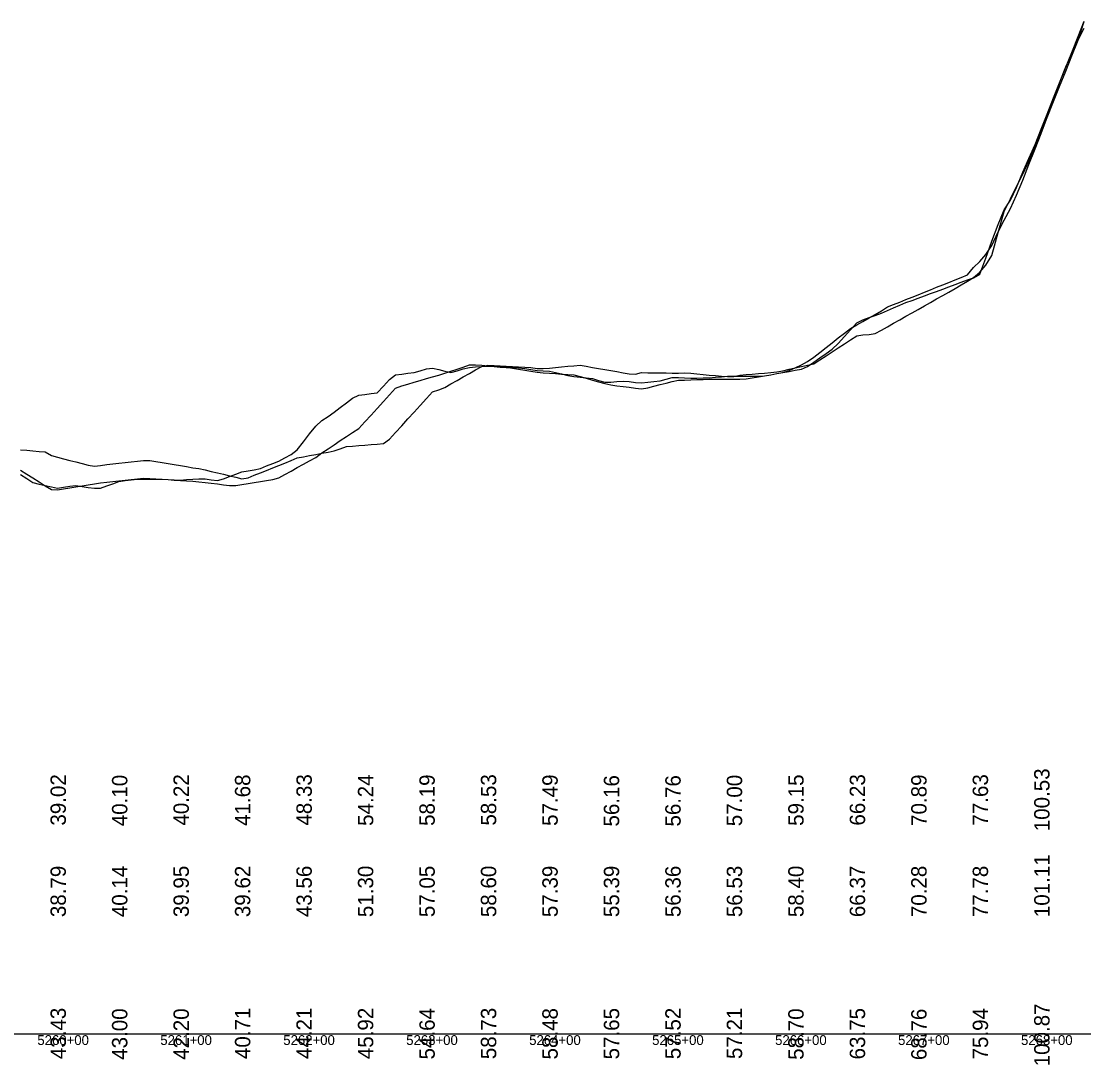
# Model space of a CAD drawing. Extents: x 2147288 to 2220488, y 740833 to 759333.
# Drawn here: x 2208344 to 2209208, y 750058 to 750907 of the extents above; entities that cross this region are included whole.
import ezdxf

# ---------------------------------------------------------------- set-up
doc = ezdxf.new("R2010")
doc.units = 0
for name, color, linetype in [('RD_DDB_Profile_EX', 7, 'Continuous'), ('RD_DDB_StaTX', 7, 'Continuous'), ('RD_DDB_StripGrade', 7, 'Continuous'), ('RD_GPK_Profile_Cell', 7, 'Continuous')]:
    doc.layers.add(name, color=color, linetype=linetype)

msp = doc.modelspace()

# ---------------------------------------------------------------- linework, layer by layer
at = {"layer": 'RD_DDB_Profile_EX'}
for points in [[(2209038.28, 750667.96), (2209043.28, 750669.8), (2209048.28, 750671.78), (2209053.28, 750673.95), (2209058.28, 750676.12), (2209063.28, 750678.3), (2209068.28, 750680.11), (2209073.28, 750681.95), (2209078.28, 750683.8), (2209083.28, 750685.65), (2209088.28, 750687.49), (2209093.28, 750689.34), (2209098.28, 750691.18), (2209103.28, 750693.03), (2209108.28, 750694.88), (2209113.28, 750696.72), (2209118.28, 750698.57), (2209123.28, 750701.42), (2209128.28, 750714.57), (2209133.28, 750728.43), (2209138.28, 750741.77), (2209143.28, 750753.91), (2209148.28, 750761.73), (2209153.28, 750771.85), (2209158.28, 750784.47), (2209163.28, 750795.68), (2209168.28, 750806.97), (2209173.28, 750819.31), (2209178.28, 750831.64), (2209183.28, 750844.78), (2209188.28, 750857.17), (2209193.28, 750869.9), (2209198.28, 750881.85), (2209203.28, 750894.73), (2209208.28, 750907.2)], [(2209038.28, 750668.73), (2209043.28, 750671.59), (2209048.28, 750674.76), (2209053.28, 750676.68), (2209058.28, 750678.7), (2209063.28, 750680.72), (2209068.28, 750682.75), (2209073.28, 750684.76), (2209078.28, 750686.77), (2209083.28, 750688.78), (2209088.28, 750690.79), (2209093.28, 750692.8), (2209098.28, 750694.8), (2209103.28, 750696.81), (2209108.28, 750698.82), (2209113.28, 750700.79), (2209118.28, 750706.97), (2209123.28, 750711.78), (2209128.28, 750717.48), (2209133.28, 750724.76), (2209138.28, 750735.98), (2209143.28, 750745.46), (2209148.28, 750754.92), (2209153.28, 750765.76), (2209158.28, 750777.8), (2209163.28, 750790.58), (2209168.28, 750803.36), (2209173.28, 750815.96), (2209178.28, 750828.78), (2209183.28, 750841.82), (2209188.28, 750854.22), (2209193.28, 750866.63), (2209198.28, 750878.95), (2209203.28, 750891.79), (2209208.28, 750906.99)], [(2209038.28, 750653.09), (2209043.28, 750655.91), (2209048.28, 750658.73), (2209053.28, 750661.55), (2209058.28, 750664.37), (2209063.28, 750667.2), (2209068.28, 750670.02), (2209073.28, 750672.84), (2209078.28, 750675.66), (2209083.28, 750678.48), (2209088.28, 750681.31), (2209093.28, 750684.13), (2209098.28, 750686.95), (2209103.28, 750689.84), (2209108.28, 750692.83), (2209113.28, 750695.82), (2209118.28, 750698.8), (2209123.28, 750703.1), (2209128.28, 750708.65), (2209133.28, 750716.64), (2209138.28, 750735.25), (2209143.28, 750752.44), (2209148.28, 750762.65), (2209153.28, 750772.87), (2209158.28, 750782.74), (2209163.28, 750793.26), (2209168.28, 750805.12), (2209173.28, 750816.89), (2209178.28, 750830.18), (2209183.28, 750843.74), (2209188.28, 750856.99), (2209193.28, 750870.1), (2209198.28, 750881.01), (2209203.28, 750892.17), (2209208.28, 750901.7)], [(2208538.28, 750543.51), (2208543.28, 750545.49), (2208548.28, 750547.46), (2208553.28, 750549.43), (2208558.28, 750552.06), (2208563.28, 750554.86), (2208568.28, 750558.69), (2208573.28, 750565.1), (2208578.28, 750571.51), (2208583.28, 750577.92), (2208588.28, 750582.41), (2208593.28, 750585.73), (2208598.28, 750589.09), (2208603.28, 750592.94), (2208608.28, 750596.79), (2208613.28, 750600.64), (2208618.28, 750603.04), (2208623.28, 750603.66), (2208628.28, 750604.29), (2208633.28, 750604.91), (2208638.28, 750610.26), (2208643.28, 750615.72), (2208648.28, 750619.59), (2208653.28, 750620.22), (2208658.28, 750620.84), (2208663.28, 750621.47), (2208668.28, 750622.89), (2208673.28, 750624.41), (2208678.28, 750625.09), (2208683.28, 750623.85), (2208688.28, 750622.6), (2208693.28, 750621.36), (2208698.28, 750622.73), (2208703.28, 750624.41), (2208708.28, 750625.56), (2208713.28, 750625.96), (2208718.28, 750626.36), (2208723.28, 750626.66), (2208728.28, 750626.29), (2208733.28, 750625.92), (2208738.28, 750625.66), (2208743.28, 750625.44), (2208748.28, 750625.21), (2208753.28, 750624.73), (2208758.28, 750623.9), (2208763.28, 750623.12), (2208768.28, 750622.79), (2208773.28, 750622.45), (2208778.28, 750621.51), (2208783.28, 750620.34), (2208788.28, 750619.16), (2208793.28, 750618.27), (2208798.28, 750617.74), (2208803.28, 750617.2), (2208808.28, 750616.46), (2208813.28, 750615.04), (2208818.28, 750613.63), (2208823.28, 750613.7), (2208828.28, 750614.04), (2208833.28, 750614.39), (2208838.28, 750614.05), (2208843.28, 750613.4), (2208848.28, 750613.11), (2208853.28, 750613.64), (2208858.28, 750614.16), (2208863.28, 750614.78), (2208868.28, 750616.05), (2208873.28, 750617.33), (2208878.28, 750617.37), (2208883.28, 750617.11), (2208888.28, 750616.86), (2208893.28, 750616.83), (2208898.28, 750617.01), (2208903.28, 750617.25), (2208908.28, 750617.64), (2208913.28, 750618.04), (2208918.28, 750618.44), (2208923.28, 750618.44), (2208928.28, 750618.42), (2208933.28, 750618.43), (2208938.28, 750618.46), (2208943.28, 750618.48), (2208948.28, 750618.83), (2208953.28, 750619.7), (2208958.28, 750620.59), (2208963.28, 750621.52), (2208968.28, 750623.08), (2208973.28, 750625.38), (2208978.28, 750627.67), (2208983.28, 750630.39), (2208988.28, 750633.9), (2208993.28, 750637.69), (2208998.28, 750641.69), (2209003.28, 750645.69), (2209008.28, 750649.6), (2209013.28, 750653.48), (2209018.28, 750657.27), (2209023.28, 750660.13), (2209028.28, 750663), (2209033.28, 750665.86), (2209038.28, 750668.73)], [(2208538.28, 750532.7), (2208543.28, 750533.52), (2208548.28, 750534.33), (2208553.28, 750535.69), (2208558.28, 750538.48), (2208563.28, 750541.28), (2208568.28, 750544.07), (2208573.28, 750546.87), (2208578.28, 750549.66), (2208583.28, 750552.46), (2208588.28, 750556.07), (2208593.28, 750559.39), (2208598.28, 750562.71), (2208603.28, 750566.03), (2208608.28, 750569.35), (2208613.28, 750572.67), (2208618.28, 750575.96), (2208623.28, 750581.41), (2208628.28, 750586.87), (2208633.28, 750592.32), (2208638.28, 750597.77), (2208643.28, 750603.22), (2208648.28, 750608.68), (2208653.28, 750610.49), (2208658.28, 750612), (2208663.28, 750613.51), (2208668.28, 750615.03), (2208673.28, 750616.54), (2208678.28, 750618.06), (2208683.28, 750619.17), (2208688.28, 750620.85), (2208693.28, 750622.54), (2208698.28, 750624.22), (2208703.28, 750625.9), (2208708.28, 750627.58), (2208713.28, 750627.75), (2208718.28, 750627.38), (2208723.28, 750627.02), (2208728.28, 750626.65), (2208733.28, 750626.28), (2208738.28, 750625.89), (2208743.28, 750625.07), (2208748.28, 750624.24), (2208753.28, 750623.41), (2208758.28, 750622.58), (2208763.28, 750621.75), (2208768.28, 750621.21), (2208773.28, 750620.88), (2208778.28, 750620.54), (2208783.28, 750620.21), (2208788.28, 750619.87), (2208793.28, 750619.55), (2208798.28, 750618.17), (2208803.28, 750616.75), (2208808.28, 750615.33), (2208813.28, 750613.92), (2208818.28, 750612.5), (2208823.28, 750611.39), (2208828.28, 750610.73), (2208833.28, 750610.08), (2208838.28, 750609.43), (2208843.28, 750608.78), (2208848.28, 750608.13), (2208853.28, 750609.05), (2208858.28, 750610.32), (2208863.28, 750611.6), (2208868.28, 750612.87), (2208873.28, 750614.15), (2208878.28, 750615.12), (2208883.28, 750615.3), (2208888.28, 750615.48), (2208893.28, 750615.67), (2208898.28, 750615.85), (2208903.28, 750616.04), (2208908.28, 750616.04), (2208913.28, 750616.02), (2208918.28, 750616), (2208923.28, 750615.98), (2208928.28, 750615.97), (2208933.28, 750616.2), (2208938.28, 750617.07), (2208943.28, 750617.95), (2208948.28, 750618.82), (2208953.28, 750619.7), (2208958.28, 750620.53), (2208963.28, 750621.47), (2208968.28, 750622.4), (2208973.28, 750623.34), (2208978.28, 750624.27), (2208983.28, 750626.33), (2208988.28, 750629.78), (2208993.28, 750633.29), (2208998.28, 750636.8), (2209003.28, 750640.32), (2209008.28, 750645.04), (2209013.28, 750650.64), (2209018.28, 750656.24), (2209023.28, 750661.85), (2209028.28, 750664.27), (2209033.28, 750666.11), (2209038.28, 750667.96)], [(2208538.28, 750539.83), (2208543.28, 750541.83), (2208548.28, 750543.83), (2208553.28, 750545.82), (2208558.28, 750547.82), (2208563.28, 750549.94), (2208568.28, 750552.06), (2208573.28, 750553), (2208578.28, 750553.94), (2208583.28, 750554.89), (2208588.28, 750555.83), (2208593.28, 750556.78), (2208598.28, 750557.72), (2208603.28, 750559.39), (2208608.28, 750561.15), (2208613.28, 750561.56), (2208618.28, 750561.97), (2208623.28, 750562.39), (2208628.28, 750562.8), (2208633.28, 750563.21), (2208638.28, 750563.62), (2208643.28, 750567.12), (2208648.28, 750572.64), (2208653.28, 750578.16), (2208658.28, 750583.68), (2208663.28, 750589.2), (2208668.28, 750594.72), (2208673.28, 750600.24), (2208678.28, 750605.76), (2208683.28, 750607.29), (2208688.28, 750609.31), (2208693.28, 750612.16), (2208698.28, 750615), (2208703.28, 750617.85), (2208708.28, 750620.69), (2208713.28, 750623.53), (2208718.28, 750626.38), (2208723.28, 750627.55), (2208728.28, 750627.24), (2208733.28, 750626.96), (2208738.28, 750626.68), (2208743.28, 750626.39), (2208748.28, 750626.11), (2208753.28, 750625.83), (2208758.28, 750625.52), (2208763.28, 750624.76), (2208768.28, 750624.61), (2208773.28, 750625.08), (2208778.28, 750625.55), (2208783.28, 750626.02), (2208788.28, 750626.49), (2208793.28, 750626.96), (2208798.28, 750627.44), (2208803.28, 750626.7), (2208808.28, 750625.65), (2208813.28, 750624.78), (2208818.28, 750623.91), (2208823.28, 750623.05), (2208828.28, 750622.18), (2208833.28, 750621.31), (2208838.28, 750620.5), (2208843.28, 750620.1), (2208848.28, 750621.4), (2208853.28, 750621.33), (2208858.28, 750621.26), (2208863.28, 750621.18), (2208868.28, 750621.1), (2208873.28, 750621.03), (2208878.28, 750620.95), (2208883.28, 750621.09), (2208888.28, 750620.97), (2208893.28, 750620.45), (2208898.28, 750619.93), (2208903.28, 750619.42), (2208908.28, 750618.9), (2208913.28, 750618.38), (2208918.28, 750618.19), (2208923.28, 750618.33), (2208928.28, 750619.21), (2208933.28, 750619.71), (2208938.28, 750620.14), (2208943.28, 750620.56), (2208948.28, 750620.98), (2208953.28, 750621.4), (2208958.28, 750622), (2208963.28, 750622.93), (2208968.28, 750624.06), (2208973.28, 750625.18), (2208978.28, 750626.3), (2208983.28, 750627.43), (2208988.28, 750628.55), (2208993.28, 750631.75), (2208998.28, 750635), (2209003.28, 750638.26), (2209008.28, 750641.52), (2209013.28, 750644.78), (2209018.28, 750648.03), (2209023.28, 750651.29), (2209028.28, 750652.05), (2209033.28, 750652.3), (2209038.28, 750653.09)], [(2208343.28, 750558.64), (2208348.28, 750558.18), (2208353.28, 750557.73), (2208358.28, 750557.27), (2208363.28, 750556.82), (2208368.28, 750553.92), (2208373.28, 750552.62), (2208378.28, 750551.31), (2208383.28, 750550.01), (2208388.28, 750548.7), (2208393.28, 750547.4), (2208398.28, 750546.09), (2208403.28, 750545.2), (2208408.28, 750545.95), (2208413.28, 750546.5), (2208418.28, 750547.04), (2208423.28, 750547.59), (2208428.28, 750548.13), (2208433.28, 750548.68), (2208438.28, 750549.23), (2208443.28, 750549.77), (2208448.28, 750549.85), (2208453.28, 750549.13), (2208458.28, 750548.28), (2208463.28, 750547.43), (2208468.28, 750546.58), (2208473.28, 750545.74), (2208478.28, 750544.89), (2208483.28, 750544.04), (2208488.28, 750543.39), (2208493.28, 750542.24), (2208498.28, 750541.05), (2208503.28, 750539.86), (2208508.28, 750538.67), (2208513.28, 750537.48), (2208518.28, 750536.29), (2208523.28, 750535.1), (2208528.28, 750535.83), (2208533.28, 750537.83), (2208538.28, 750539.83)], [(2208343.28, 750538.39), (2208348.28, 750535.23), (2208353.28, 750532.07), (2208358.28, 750530.5), (2208363.28, 750529.49), (2208368.28, 750528.48), (2208373.28, 750527.47), (2208378.28, 750528.09), (2208383.28, 750528.9), (2208388.28, 750529.56), (2208393.28, 750528.8), (2208398.28, 750528.04), (2208403.28, 750527.28), (2208408.28, 750527.45), (2208413.28, 750529.22), (2208418.28, 750531), (2208423.28, 750532.77), (2208428.28, 750533.62), (2208433.28, 750534.15), (2208438.28, 750534.69), (2208443.28, 750534.81), (2208448.28, 750534.82), (2208453.28, 750534.82), (2208458.28, 750534.77), (2208463.28, 750534.45), (2208468.28, 750534.13), (2208473.28, 750533.96), (2208478.28, 750534.32), (2208483.28, 750534.68), (2208488.28, 750535.04), (2208493.28, 750534.85), (2208498.28, 750534.28), (2208503.28, 750533.71), (2208508.28, 750534.97), (2208513.28, 750536.86), (2208518.28, 750538.76), (2208523.28, 750540.57), (2208528.28, 750541.38), (2208533.28, 750542.2), (2208538.28, 750543.51)], [(2208343.28, 750542), (2208348.28, 750538.84), (2208353.28, 750535.68), (2208358.28, 750532.51), (2208363.28, 750529.35), (2208368.28, 750526.19), (2208373.28, 750526.11), (2208378.28, 750526.92), (2208383.28, 750527.73), (2208388.28, 750528.54), (2208393.28, 750529.35), (2208398.28, 750530.17), (2208403.28, 750530.98), (2208408.28, 750531.67), (2208413.28, 750532.21), (2208418.28, 750532.74), (2208423.28, 750533.28), (2208428.28, 750533.82), (2208433.28, 750534.35), (2208438.28, 750534.89), (2208443.28, 750535.43), (2208448.28, 750535.31), (2208453.28, 750534.99), (2208458.28, 750534.66), (2208463.28, 750534.34), (2208468.28, 750534.02), (2208473.28, 750533.69), (2208478.28, 750533.37), (2208483.28, 750533.07), (2208488.28, 750532.5), (2208493.28, 750531.93), (2208498.28, 750531.36), (2208503.28, 750530.79), (2208508.28, 750530.22), (2208513.28, 750529.65), (2208518.28, 750529.45), (2208523.28, 750530.27), (2208528.28, 750531.08), (2208533.28, 750531.89), (2208538.28, 750532.7)]]:
    msp.add_lwpolyline(points, dxfattribs=at)
at = {"layer": 'RD_GPK_Profile_Cell'}
msp.add_line((2198888.28, 750083.43), (2220488.28, 750083.43), dxfattribs=at)

# ---------------------------------------------------------------- texts
at = {"layer": 'RD_DDB_Profile_EX'}
for s, p in [('100.53', (2209180.08, 750248.3)), ('39.02', (2208380.08, 750252.89)), ('40.10', (2208430.08, 750252.38)), ('40.22', (2208480.08, 750252.89)), ('41.68', (2208530.08, 750252.64)), ('48.33', (2208580.08, 750252.89)), ('54.24', (2208630.08, 750252.66)), ('58.19', (2208680.08, 750252.64)), ('58.53', (2208730.08, 750252.89)), ('57.49', (2208780.08, 750252.64)), ('56.16', (2208830.08, 750252.13)), ('56.76', (2208880.08, 750252.13)), ('57.00', (2208930.08, 750252.38)), ('59.15', (2208980.08, 750252.69)), ('66.23', (2209030.08, 750252.89)), ('70.89', (2209080.08, 750252.64)), ('77.63', (2209130.08, 750252.89)), ('100.87', (2209180.08, 750057.08)), ('43.43', (2208380.08, 750062.89)), ('43.00', (2208430.08, 750062.38)), ('42.20', (2208480.08, 750062.38)), ('40.71', (2208530.08, 750063)), ('44.21', (2208580.08, 750063)), ('45.92', (2208630.08, 750062.89)), ('54.64', (2208680.08, 750062.66)), ('58.73', (2208730.08, 750062.89)), ('58.48', (2208780.08, 750062.64)), ('57.65', (2208830.08, 750062.69)), ('57.52', (2208880.08, 750062.89)), ('57.21', (2208930.08, 750063)), ('58.70', (2208980.08, 750062.38)), ('63.75', (2209030.08, 750062.69)), ('68.76', (2209080.08, 750062.13)), ('75.94', (2209130.08, 750062.66))]:
    msp.add_text(s, height=12.5, rotation=90, dxfattribs=at).set_placement(p)
at = {"layer": 'RD_DDB_StaTX'}
for s, p in [('5260+00', (2208356.88, 750074.43)), ('5260+00', (2208356.88, 750074.43)), ('5260+00', (2208356.88, 750074.43)), ('5261+00', (2208456.88, 750074.43)), ('5261+00', (2208456.88, 750074.43)), ('5261+00', (2208456.88, 750074.43)), ('5262+00', (2208556.88, 750074.43)), ('5262+00', (2208556.88, 750074.43)), ('5262+00', (2208556.88, 750074.43)), ('5263+00', (2208656.88, 750074.43)), ('5263+00', (2208656.88, 750074.43)), ('5263+00', (2208656.88, 750074.43)), ('5264+00', (2208756.88, 750074.43)), ('5264+00', (2208756.88, 750074.43)), ('5264+00', (2208756.88, 750074.43)), ('5265+00', (2208856.88, 750074.43)), ('5265+00', (2208856.88, 750074.43)), ('5265+00', (2208856.88, 750074.43)), ('5266+00', (2208956.88, 750074.43)), ('5266+00', (2208956.88, 750074.43)), ('5266+00', (2208956.88, 750074.43)), ('5267+00', (2209056.88, 750074.43)), ('5267+00', (2209056.88, 750074.43)), ('5267+00', (2209056.88, 750074.43)), ('5268+00', (2209156.88, 750074.43)), ('5268+00', (2209156.88, 750074.43)), ('5268+00', (2209156.88, 750074.43))]:
    msp.add_text(s, height=8, dxfattribs=at).set_placement(p)
at = {"layer": 'RD_DDB_StripGrade'}
for s, p in [('101.11', (2209180.08, 750178.43)), ('38.79', (2208380.08, 750178.43)), ('40.14', (2208430.08, 750178.43)), ('39.95', (2208480.08, 750178.43)), ('39.62', (2208530.08, 750178.43)), ('43.56', (2208580.08, 750178.43)), ('51.30', (2208630.08, 750178.43)), ('57.05', (2208680.08, 750178.43)), ('58.60', (2208730.08, 750178.43)), ('57.39', (2208780.08, 750178.43)), ('55.39', (2208830.08, 750178.43)), ('56.36', (2208880.08, 750178.43)), ('56.53', (2208930.08, 750178.43)), ('58.40', (2208980.08, 750178.43)), ('66.37', (2209030.08, 750178.43)), ('70.28', (2209080.08, 750178.43)), ('77.78', (2209130.08, 750178.43))]:
    msp.add_text(s, height=12.5, rotation=90, dxfattribs=at).set_placement(p)

doc.saveas('drawing.dxf')
